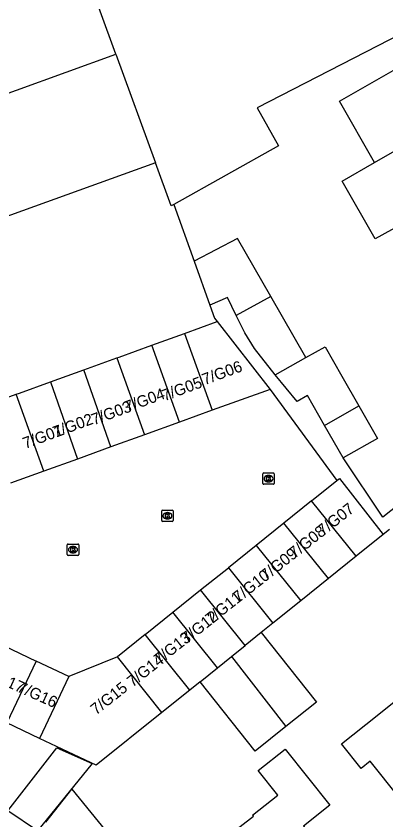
# Model space of a CAD drawing. Extents: x 159503 to 160347, y 382525 to 383272.
# Drawn here: x 159751.6 to 159784.1, y 383005.9 to 383076.7 of the extents above; entities that cross this region are included whole.
import ezdxf

# ---------------------------------------------------------------- set-up
doc = ezdxf.new("R2010")
doc.units = 0
for name, color, linetype in [('IMGEO_Kolk', 7, 'Continuous'), ('IMGEO_Pand', 7, 'Continuous'), ('IMGEO_Pand_nummerreeks', 7, 'Continuous'), ('IMGEO_Voetpad_open', 7, 'Continuous')]:
    doc.layers.add(name, color=color, linetype=linetype)

msp = doc.modelspace()

# ---------------------------------------------------------------- linework, layer by layer
at = {"layer": 'IMGEO_Kolk'}
for p, q in [((159773.314, 383035.542), (159773.314, 383036.394)), ((159773.389, 383036.468), (159774.241, 383036.468)), ((159773.802, 383036.248), (159773.827, 383036.248)), ((159774.315, 383036.394), (159774.315, 383035.542)), ((159774.241, 383035.468), (159773.389, 383035.468)), ((159773.825, 383035.688), (159773.8, 383035.688)), ((159764.409, 383032.266), (159764.409, 383033.118)), ((159764.484, 383033.192), (159765.336, 383033.192)), ((159764.897, 383032.972), (159764.922, 383032.972)), ((159765.41, 383033.118), (159765.41, 383032.266)), ((159765.336, 383032.192), (159764.484, 383032.192)), ((159764.92, 383032.412), (159764.895, 383032.412)), ((159756.1, 383029.282), (159756.1, 383030.134)), ((159756.175, 383030.208), (159757.027, 383030.208)), ((159756.588, 383029.988), (159756.613, 383029.988)), ((159757.101, 383030.134), (159757.101, 383029.282)), ((159757.027, 383029.208), (159756.175, 383029.208)), ((159756.611, 383029.428), (159756.586, 383029.428))]:
    msp.add_line(p, q, dxfattribs=at)
for points in [[(159773.314, 383035.542), (159773.314, 383036.394)], [(159773.389, 383036.468), (159774.241, 383036.468)], [(159773.635, 383036.168), (159773.758, 383036.168), (159773.758, 383036.017), (159773.888, 383036.168), (159774.052, 383036.168), (159773.906, 383036.017), (159774.059, 383035.768), (159773.907, 383035.768), (159773.822, 383035.932), (159773.758, 383035.865), (159773.758, 383035.768), (159773.635, 383035.768), (159773.635, 383036.168)], [(159774.315, 383036.394), (159774.315, 383035.542)], [(159774.241, 383035.468), (159773.389, 383035.468)], [(159764.409, 383032.266), (159764.409, 383033.118)], [(159764.484, 383033.192), (159765.336, 383033.192)], [(159764.73, 383032.892), (159764.853, 383032.892), (159764.853, 383032.741), (159764.983, 383032.892), (159765.147, 383032.892), (159765.001, 383032.741), (159765.154, 383032.492), (159765.002, 383032.492), (159764.917, 383032.656), (159764.853, 383032.589), (159764.853, 383032.492), (159764.73, 383032.492), (159764.73, 383032.892)], [(159765.41, 383033.118), (159765.41, 383032.266)], [(159765.336, 383032.192), (159764.484, 383032.192)], [(159756.1, 383029.282), (159756.1, 383030.134)], [(159756.175, 383030.208), (159757.027, 383030.208)], [(159756.421, 383029.908), (159756.544, 383029.908), (159756.544, 383029.757), (159756.674, 383029.908), (159756.838, 383029.908), (159756.692, 383029.757), (159756.845, 383029.508), (159756.693, 383029.508), (159756.608, 383029.672), (159756.544, 383029.605), (159756.544, 383029.508), (159756.421, 383029.508), (159756.421, 383029.908)], [(159757.101, 383030.134), (159757.101, 383029.282)], [(159757.027, 383029.208), (159756.175, 383029.208)]]:
    msp.add_lwpolyline(points, dxfattribs=at)
for centre, start, end in [((159773.391, 383036.392), 91.55205, 178.44795), ((159773.391, 383036.392), 91.55205, 178.44795), ((159774.239, 383036.392), 1.55205, 88.44795), ((159774.239, 383036.392), 1.55205, 88.44795), ((159773.391, 383035.544), 181.55205, 268.44795), ((159773.391, 383035.544), 181.55205, 268.44795), ((159774.239, 383035.544), 271.55205, 358.44795), ((159774.239, 383035.544), 271.55205, 358.44795), ((159764.486, 383033.116), 91.55205, 178.44795), ((159764.486, 383033.116), 91.55205, 178.44795), ((159765.334, 383033.116), 1.55205, 88.44795), ((159765.334, 383033.116), 1.55205, 88.44795), ((159764.486, 383032.268), 181.55205, 268.44795), ((159764.486, 383032.268), 181.55205, 268.44795), ((159765.334, 383032.268), 271.55205, 358.44795), ((159765.334, 383032.268), 271.55205, 358.44795), ((159756.177, 383030.132), 91.55205, 178.44795), ((159756.177, 383030.132), 91.55205, 178.44795), ((159757.025, 383030.132), 1.55205, 88.44795), ((159757.025, 383030.132), 1.55205, 88.44795), ((159756.177, 383029.284), 181.55205, 268.44795), ((159756.177, 383029.284), 181.55205, 268.44795), ((159757.025, 383029.284), 271.55205, 358.44795), ((159757.025, 383029.284), 271.55205, 358.44795)]:
    msp.add_arc(centre, 0.0765, start, end, dxfattribs=at)
for centre, major_axis, ratio, start_param, end_param in [((159773.801, 383035.968), (-0.387, 0.002), 0.722429, 4.712389, 7.853982), ((159773.826, 383035.968), (-0.39, 0.002), 0.717154, 1.570796, 4.712389), ((159764.896, 383032.692), (-0.387, 0.002), 0.722429, 4.712389, 7.853982), ((159764.921, 383032.692), (-0.39, 0.002), 0.717154, 1.570796, 4.712389), ((159756.587, 383029.708), (-0.387, 0.002), 0.722429, 4.712389, 7.853982), ((159756.612, 383029.708), (-0.39, 0.002), 0.717154, 1.570796, 4.712389)]:
    msp.add_ellipse(centre, major_axis=major_axis, ratio=ratio, start_param=start_param, end_param=end_param, dxfattribs=at)
at = {"layer": 'IMGEO_Pand'}
for points in [[(159760.373, 383073.343), (159756.226, 383084.731)], [(159791.014, 383077.997), (159786.569, 383075.708), (159772.824, 383068.631), (159774.7, 383065.269), (159765.469, 383060.121)], [(159783.144, 383063.808), (159780.054, 383069.208), (159785.392, 383072.262), (159789.731, 383074.745), (159792.821, 383069.345)], [(159734.103, 383063.845), (159760.373, 383073.343)], [(159760.373, 383073.343), (159763.853, 383063.79)], [(159783.144, 383063.808), (159792.821, 383069.345)], [(159763.853, 383063.79), (159737.559, 383054.283)], [(159765.469, 383060.121), (159765.237, 383059.991), (159763.853, 383063.79)], [(159786.087, 383058.664), (159783.206, 383057.077), (159780.29, 383062.175), (159783.144, 383063.808)], [(159765.469, 383060.121), (159767.258, 383055.117)], [(159774.005, 383052.009), (159771.087, 383057.109), (159767.258, 383055.117)], [(159767.258, 383055.117), (159768.638, 383051.258)], [(159770.953, 383050.328), (159770.21, 383051.92), (159768.638, 383051.258)], [(159774.005, 383052.009), (159770.953, 383050.328)], [(159777.086, 383046.623), (159774.005, 383052.009)], [(159768.638, 383051.258), (159769.048, 383050.112), (159769.296, 383049.793)], [(159774.391, 383045.107), (159772.567, 383047.416), (159771.726, 383048.815), (159770.953, 383050.328)], [(159766.418, 383048.753), (159769.296, 383049.793)], [(159769.296, 383049.793), (159773.943, 383043.823)], [(159763.539, 383047.712), (159766.418, 383048.753)], [(159766.418, 383048.753), (159768.863, 383041.986)], [(159760.446, 383046.594), (159760.661, 383046.672), (159763.539, 383047.712)], [(159765.985, 383040.946), (159763.539, 383047.712)], [(159777.086, 383046.623), (159778.786, 383047.579), (159780.26, 383045.002), (159781.759, 383042.383)], [(159757.563, 383045.552), (159760.446, 383046.594)], [(159760.446, 383046.594), (159762.891, 383039.827)], [(159774.391, 383045.107), (159777.086, 383046.623)], [(159754.619, 383044.488), (159757.563, 383045.552)], [(159759.941, 383038.76), (159757.563, 383045.552)], [(159778.747, 383040.659), (159777.248, 383043.279), (159776.337, 383042.758), (159774.391, 383045.107)], [(159751.595, 383043.394), (159751.879, 383043.497), (159754.619, 383044.488)], [(159754.619, 383044.488), (159756.991, 383037.694)], [(159773.943, 383043.823), (159768.863, 383041.986)], [(159748.633, 383042.324), (159748.835, 383042.397), (159751.595, 383043.394)], [(159754.041, 383036.627), (159751.595, 383043.394)], [(159768.863, 383041.986), (159765.985, 383040.946)], [(159778.747, 383040.659), (159781.759, 383042.383)], [(159781.759, 383042.383), (159783.401, 383039.513), (159780.389, 383037.79)], [(159765.985, 383040.946), (159762.891, 383039.827)], [(159780.389, 383037.79), (159778.747, 383040.659)], [(159762.891, 383039.827), (159759.941, 383038.76)], [(159759.941, 383038.76), (159756.991, 383037.694)], [(159756.991, 383037.694), (159754.041, 383036.627)], [(159754.041, 383036.627), (159751.091, 383035.561)], [(159777.604, 383034.017), (159779.811, 383035.792)], [(159779.811, 383035.792), (159780.046, 383035.981), (159783.896, 383031.034)], [(159777.604, 383034.017), (159775.161, 383032.052)], [(159781.532, 383029.133), (159777.604, 383034.017)], [(159775.161, 383032.052), (159772.719, 383030.088)], [(159779.089, 383027.168), (159775.161, 383032.052)], [(159783.896, 383031.034), (159781.532, 383029.133)], [(159772.719, 383030.088), (159770.276, 383028.124)], [(159772.719, 383030.088), (159776.646, 383025.204)], [(159781.532, 383029.133), (159779.089, 383027.168)], [(159767.834, 383026.159), (159770.276, 383028.124)], [(159770.276, 383028.124), (159774.204, 383023.24)], [(159779.089, 383027.168), (159776.646, 383025.204)], [(159765.391, 383024.195), (159767.834, 383026.159)], [(159771.761, 383021.275), (159767.834, 383026.159)], [(159776.646, 383025.204), (159774.204, 383023.24)], [(159762.948, 383022.23), (159765.391, 383024.195)], [(159769.319, 383019.311), (159765.391, 383024.195)], [(159774.204, 383023.24), (159773.162, 383022.402)], [(159762.948, 383022.23), (159760.506, 383020.266)], [(159766.876, 383017.347), (159762.948, 383022.23)], [(159773.162, 383022.402), (159771.761, 383021.275)], [(159773.162, 383022.402), (159778.043, 383016.28), (159775.345, 383014.129)], [(159750.492, 383021.257), (159753.36, 383019.897)], [(159770.54, 383020.293), (159771.761, 383021.275)], [(159753.36, 383019.897), (159750.775, 383014.446)], [(159756.228, 383018.537), (159753.36, 383019.897)], [(159760.506, 383020.266), (159756.228, 383018.537)], [(159764.433, 383015.383), (159760.506, 383020.266)], [(159769.319, 383019.311), (159770.54, 383020.293)], [(159770.54, 383020.293), (159775.345, 383014.129)], [(159767.784, 383018.077), (159769.319, 383019.311)], [(159756.228, 383018.537), (159753.643, 383013.086)], [(159767.784, 383018.077), (159766.876, 383017.347)], [(159775.345, 383014.129), (159772.647, 383011.978), (159767.784, 383018.077)], [(159766.876, 383017.347), (159764.433, 383015.383)], [(159793.71, 383008.158), (159788.437, 383003.961), (159785.323, 383007.874), (159782.767, 383011.085), (159781.958, 383010.441), (159780.23, 383012.611), (159783.363, 383015.106), (159784.429, 383015.955), (159786.145, 383017.31), (159786.318, 383017.448)], [(159764.433, 383015.383), (159758.634, 383010.719), (159753.643, 383013.086)], [(159753.643, 383013.086), (159750.775, 383014.446)], [(159758.283, 383010.865), (159753.467, 383004.946), (159750.876, 383006.697), (159755.183, 383012.265), (159758.283, 383010.865)], [(159769.487, 383003.92), (159772.486, 383006.228), (159772.407, 383006.327), (159774.63, 383008.091), (159772.911, 383010.258), (159775.283, 383012.14), (159779.201, 383007.202), (159776.897, 383005.374), (159778.957, 383002.782), (159779.951, 383001.528), (159781.162, 383000), (159782.063, 382998.864), (159776.807, 382994.694)], [(159754.195, 383005.716), (159756.505, 383008.608), (159762.795, 383000.858), (159759.987, 382998.579)]]:
    msp.add_lwpolyline(points, dxfattribs=at)
at = {"layer": 'IMGEO_Voetpad_open'}
for points in [[(159773.943, 383043.823), (159779.811, 383035.792)], [(159795.222, 383042.699), (159795.675, 383041.908), (159783.872, 383032.57), (159780.389, 383037.79)], [(159784.459, 383031.484), (159783.896, 383031.034)]]:
    msp.add_lwpolyline(points, dxfattribs=at)

# ---------------------------------------------------------------- texts
at = {"layer": 'IMGEO_Pand_nummerreeks'}
for s, rotation, p in [('7/G06', 20.30263, (159768.185, 383044.195)), ('7/G05', 20.30263, (159764.65, 383042.781)), ('7/G04', 20.30263, (159761.367, 383041.779)), ('7/G03', 20.30263, (159758.434, 383040.659)), ('7/G02', 20.30263, (159755.047, 383039.554)), ('7/G01', 20.30263, (159752.399, 383038.574)), ('7/G07', 38.29077, (159778.596, 383030.866)), ('7/G08', 38.29016, (159776.094, 383028.89)), ('7/G09', 38.29016, (159773.584, 383026.909)), ('7/G10', 38.29016, (159771.156, 383024.992)), ('7/G11', 38.29016, (159768.736, 383023.081)), ('7/G12', 38.29016, (159766.635, 383021.389)), ('7/G13', 38.29016, (159764.218, 383019.525)), ('7/G14', 38.29016, (159761.846, 383017.557)), ('7/G17', 335.75407, (159748.73, 383018.548)), ('7/G16', 335.75407, (159751.608, 383017.251)), ('7/G15', 38.29016, (159758.631, 383015.104))]:
    msp.add_text(s, height=1, rotation=rotation, dxfattribs=at).set_placement(p)

doc.saveas('drawing.dxf')
